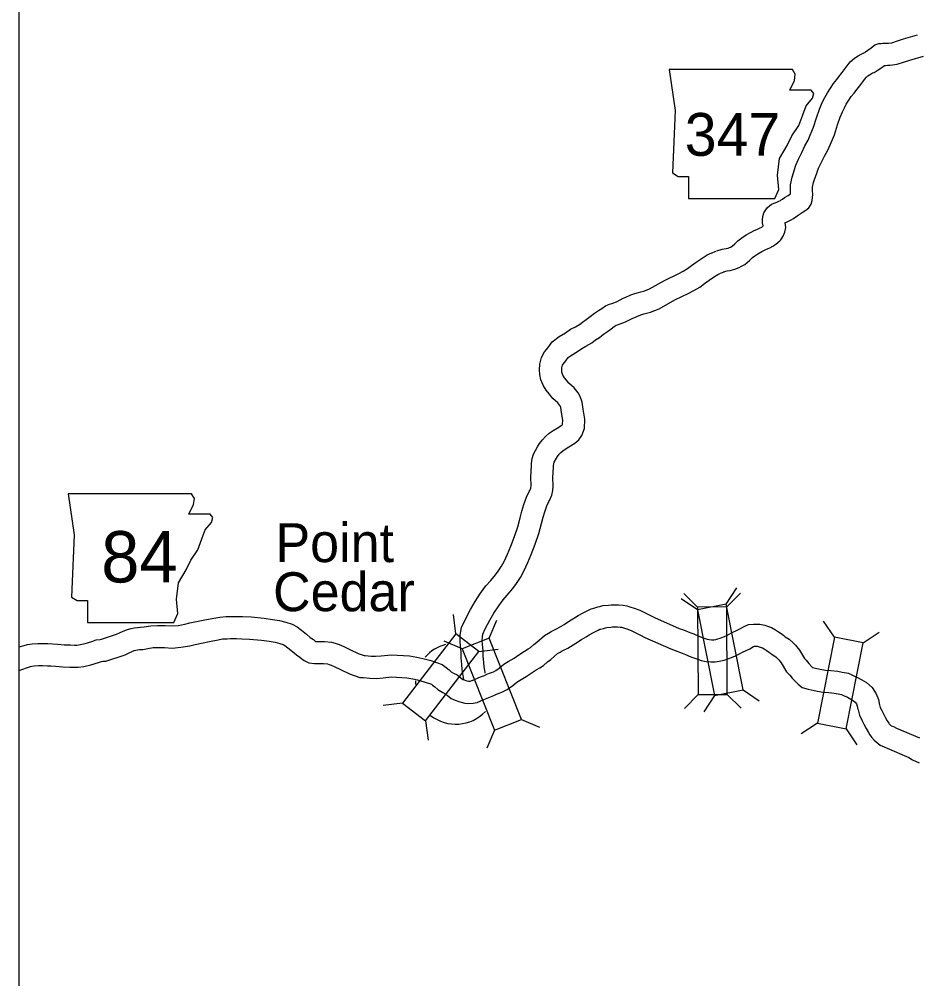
# Model space of a CAD drawing. Extents: x 1373862 to 1377080, y 1164775 to 1170415.
# Drawn here: x 1373884.5 to 1374006.5, y 1170176 to 1170306.2 of the extents above; entities that cross this region are included whole.
import ezdxf

# ---------------------------------------------------------------- set-up
doc = ezdxf.new("R2010")
doc.units = 0
doc.layers.add('1', color=7, linetype='Continuous')
doc.layers.add('Default', color=7, linetype='Continuous')

msp = doc.modelspace()

# ---------------------------------------------------------------- linework, layer by layer
at = {"layer": '1'}
msp.add_lwpolyline([(1373884.49, 1170388.77), (1374613.88, 1170388.77), (1374613.88, 1169861.94), (1373884.49, 1169861.94)], close=True, dxfattribs=at)
at = {"layer": 'Default'}
for p, q in [((1373976.57, 1170226.45), (1373974.69, 1170228.31)), ((1373980.44, 1170226.86), (1373981.91, 1170229.06)), ((1373980.53, 1170226.48), (1373982.38, 1170228.35)), ((1373976.55, 1170226.09), (1373974.36, 1170227.56)), ((1373943.77, 1170222.83), (1373943.43, 1170225.45)), ((1373948.29, 1170222.25), (1373949.33, 1170224.67)), ((1373995.14, 1170222.36), (1373993.67, 1170224.55)), ((1373999.03, 1170221.59), (1374001.22, 1170223.06)), ((1373944.61, 1170220.78), (1373942.19, 1170221.83)), ((1373946.9, 1170220.41), (1373949.52, 1170220.75)), ((1373982.75, 1170215.21), (1373984.94, 1170213.74)), ((1373976.64, 1170214.57), (1373974.79, 1170212.69)), ((1373978.86, 1170214.44), (1373977.4, 1170212.25)), ((1373980.6, 1170214.6), (1373982.48, 1170212.74)), ((1373936.51, 1170213.42), (1373933.9, 1170213.08)), ((1373952.69, 1170211.21), (1373955.11, 1170210.17)), ((1373939.65, 1170211), (1373939.99, 1170208.38)), ((1373992.84, 1170210.7), (1373990.65, 1170209.23)), ((1373996.73, 1170209.94), (1373998.2, 1170207.74)), ((1373949.01, 1170209.75), (1373947.97, 1170207.32))]:
    msp.add_line(p, q, dxfattribs=at)
for points in [[(1373979.18, 1170274.79), (1373979.91, 1170275.02), (1373980.43, 1170275.1), (1373980.73, 1170275.16), (1373980.92, 1170275.24), (1373981.05, 1170275.31), (1373981.25, 1170275.43), (1373981.62, 1170275.73), (1373982.05, 1170276.16), (1373982.57, 1170276.56), (1373983.18, 1170276.96), (1373983.84, 1170277.33), (1373984.23, 1170277.54), (1373984.62, 1170277.71), (1373985.06, 1170277.92), (1373985.28, 1170278.03), (1373985.38, 1170278.09), (1373985.49, 1170278.19), (1373985.38, 1170278.6), (1373985.37, 1170279.04), (1373985.42, 1170279.45), (1373985.58, 1170279.98), (1373985.83, 1170280.37), (1373986.07, 1170280.69), (1373986.59, 1170281.12), (1373987.11, 1170281.33), (1373987.44, 1170281.45), (1373987.6, 1170281.52), (1373987.83, 1170281.64), (1373987.93, 1170281.7), (1373988.08, 1170281.81), (1373988.38, 1170282.05), (1373988.85, 1170282.33), (1373989.07, 1170282.46), (1373989.19, 1170282.53), (1373989.19, 1170282.58), (1373989.18, 1170282.94), (1373989.18, 1170283.75), (1373989.41, 1170284.81), (1373989.57, 1170285.37), (1373989.93, 1170286.41), (1373990.26, 1170287.22), (1373990.7, 1170288.14), (1373991.13, 1170289.03), (1373991.57, 1170289.82), (1373991.87, 1170290.48), (1373992.32, 1170291.57), (1373992.71, 1170292.83), (1373993.13, 1170294.02), (1373993.5, 1170294.91), (1373993.84, 1170295.61), (1373994.19, 1170296.25), (1373994.61, 1170296.87), (1373995.01, 1170297.5), (1373995.47, 1170298.07), (1373995.71, 1170298.36), (1373996.2, 1170299.01), (1373996.61, 1170299.54), (1373996.87, 1170299.9), (1373997.3, 1170300.43), (1373997.89, 1170300.96), (1373998.35, 1170301.25), (1373998.76, 1170301.51), (1373999.13, 1170301.69), (1373999.26, 1170301.74), (1373999.37, 1170301.81), (1373999.68, 1170302.02), (1374000.12, 1170302.35), (1374000.61, 1170302.75), (1374001.19, 1170302.92), (1374001.47, 1170302.95), (1374001.73, 1170302.97), (1374001.99, 1170302.97), (1374002.26, 1170302.98), (1374002.49, 1170302.98), (1374002.96, 1170303.05), (1374003.69, 1170303.29), (1374004.51, 1170303.57), (1374006.42, 1170304.11)], [(1373980.09, 1170271.93), (1373980.58, 1170272.09), (1373980.98, 1170272.14), (1373981.65, 1170272.3), (1373982.2, 1170272.52), (1373982.53, 1170272.7), (1373982.97, 1170272.96), (1373983.62, 1170273.49), (1373984.04, 1170273.91), (1373984.32, 1170274.13), (1373984.73, 1170274.39), (1373985.28, 1170274.69), (1373985.56, 1170274.85), (1373985.85, 1170274.98), (1373986.38, 1170275.22), (1373986.78, 1170275.43), (1373987.2, 1170275.69), (1373987.72, 1170276.16), (1373987.86, 1170276.31), (1373988.18, 1170276.8), (1373988.42, 1170277.35), (1373988.55, 1170277.98), (1373988.48, 1170278.61), (1373988.47, 1170278.63), (1373988.55, 1170278.66), (1373988.92, 1170278.83), (1373989.28, 1170279.01), (1373989.59, 1170279.19), (1373989.9, 1170279.43), (1373990.09, 1170279.57), (1373990.38, 1170279.75), (1373990.62, 1170279.89), (1373990.92, 1170280.08), (1373991.28, 1170280.3), (1373991.68, 1170280.64), (1373991.97, 1170281.12), (1373992.11, 1170281.64), (1373992.15, 1170282.03), (1373992.2, 1170282.44), (1373992.18, 1170282.99), (1373992.18, 1170283.43), (1373992.32, 1170284.08), (1373992.43, 1170284.47), (1373992.74, 1170285.36), (1373993, 1170286.01), (1373993.4, 1170286.83), (1373993.8, 1170287.65), (1373994.25, 1170288.47), (1373994.62, 1170289.28), (1373995.15, 1170290.55), (1373995.56, 1170291.89), (1373995.93, 1170292.95), (1373996.23, 1170293.68), (1373996.5, 1170294.22), (1373996.76, 1170294.69), (1373997.11, 1170295.23), (1373997.44, 1170295.73), (1373997.81, 1170296.19), (1373998.07, 1170296.52), (1373998.59, 1170297.19), (1373999.01, 1170297.75), (1373999.25, 1170298.07), (1373999.49, 1170298.36), (1373999.7, 1170298.55), (1373999.93, 1170298.7), (1374000.25, 1170298.9), (1374000.32, 1170298.94), (1374000.53, 1170299.01), (1374000.97, 1170299.27), (1374001.44, 1170299.58), (1374001.94, 1170299.97), (1374002.07, 1170299.97), (1374002.34, 1170299.98), (1374002.73, 1170299.98), (1374003.66, 1170300.12), (1374004.64, 1170300.45), (1374005.39, 1170300.7), (1374007.24, 1170301.22)], [(1373944.84, 1170216.63), (1373944.77, 1170217.16), (1373944.63, 1170217.97), (1373944.59, 1170218.67), (1373944.48, 1170219.57), (1373944.46, 1170220.37), (1373944.4, 1170221.15), (1373944.35, 1170221.82), (1373944.36, 1170222.64), (1373944.54, 1170223.68), (1373945.05, 1170224.79), (1373945.73, 1170226.11), (1373946.38, 1170227.22), (1373947.12, 1170228.33), (1373947.84, 1170229.32), (1373948.49, 1170230.04), (1373949.16, 1170230.81), (1373949.52, 1170231.31), (1373949.96, 1170232.01), (1373950.31, 1170232.64), (1373950.75, 1170233.65), (1373951.2, 1170234.73), (1373951.71, 1170236.02), (1373952.16, 1170237.34), (1373952.49, 1170238.54), (1373952.7, 1170239.45), (1373952.99, 1170240.37), (1373953.36, 1170241.35), (1373953.71, 1170242.12), (1373953.79, 1170242.26), (1373953.94, 1170242.58), (1373953.95, 1170242.65), (1373953.96, 1170242.89), (1373953.93, 1170244.08), (1373954.01, 1170245.66), (1373954.04, 1170245.93), (1373954.14, 1170246.6), (1373954.3, 1170247.21), (1373954.82, 1170248.19), (1373955.13, 1170248.64), (1373955.5, 1170249.14), (1373955.91, 1170249.58), (1373956.42, 1170250.03), (1373956.99, 1170250.42), (1373957.52, 1170250.74), (1373958.16, 1170251.14), (1373958.2, 1170251.17), (1373958.23, 1170251.26), (1373958.26, 1170251.82), (1373958.1, 1170252.84), (1373957.99, 1170253.53), (1373957.91, 1170253.77), (1373957.88, 1170253.82), (1373957.62, 1170254.15), (1373956.93, 1170254.78), (1373956.42, 1170255.38), (1373956.04, 1170255.87), (1373955.67, 1170256.47), (1373955.28, 1170257.27), (1373955.16, 1170258), (1373955.12, 1170258.67), (1373955.18, 1170259.41), (1373955.4, 1170260.32), (1373955.78, 1170261.09), (1373956.28, 1170261.68), (1373956.81, 1170262.46), (1373957.78, 1170263.16), (1373958.63, 1170263.68), (1373959.34, 1170264.15), (1373959.98, 1170264.48), (1373960.56, 1170264.82), (1373960.97, 1170265.13), (1373961.46, 1170265.47), (1373962.01, 1170265.9), (1373962.6, 1170266.32), (1373963.12, 1170266.68), (1373963.57, 1170266.99), (1373964.07, 1170267.33), (1373964.5, 1170267.52), (1373965.05, 1170267.7), (1373965.55, 1170267.89), (1373966.08, 1170268.16), (1373966.49, 1170268.37), (1373966.74, 1170268.47), (1373967.53, 1170268.81), (1373968.06, 1170269.02), (1373968.53, 1170269.15), (1373968.86, 1170269.23), (1373969.26, 1170269.34), (1373970.05, 1170269.65), (1373972.09, 1170270.79), (1373974.03, 1170271.72), (1373974.6, 1170272.02), (1373975.21, 1170272.39), (1373975.75, 1170272.79), (1373976.38, 1170273.24), (1373977.04, 1170273.73), (1373977.88, 1170274.24), (1373978.51, 1170274.54), (1373979.11, 1170274.76)], [(1373947.76, 1170217.47), (1373947.74, 1170217.61), (1373947.62, 1170218.33), (1373947.57, 1170218.94), (1373947.47, 1170219.78), (1373947.46, 1170220.52), (1373947.39, 1170221.38), (1373947.35, 1170221.91), (1373947.36, 1170222.37), (1373947.43, 1170222.79), (1373947.75, 1170223.48), (1373948.35, 1170224.66), (1373948.92, 1170225.63), (1373949.58, 1170226.61), (1373950.18, 1170227.43), (1373950.74, 1170228.06), (1373951.51, 1170228.95), (1373952, 1170229.63), (1373952.53, 1170230.47), (1373953, 1170231.3), (1373953.51, 1170232.48), (1373953.98, 1170233.6), (1373954.52, 1170234.98), (1373955.03, 1170236.45), (1373955.4, 1170237.81), (1373955.6, 1170238.66), (1373955.82, 1170239.38), (1373956.13, 1170240.19), (1373956.39, 1170240.76), (1373956.47, 1170240.9), (1373956.8, 1170241.63), (1373956.94, 1170242.27), (1373956.97, 1170242.88), (1373956.93, 1170244.05), (1373957.01, 1170245.43), (1373957.02, 1170245.56), (1373957.08, 1170245.99), (1373957.12, 1170246.12), (1373957.4, 1170246.65), (1373957.56, 1170246.89), (1373957.8, 1170247.2), (1373958.01, 1170247.43), (1373958.27, 1170247.66), (1373958.61, 1170247.89), (1373959.09, 1170248.18), (1373959.92, 1170248.71), (1373960.47, 1170249.16), (1373960.88, 1170249.74), (1373961.2, 1170250.68), (1373961.28, 1170251.96), (1373961.06, 1170253.32), (1373960.91, 1170254.26), (1373960.65, 1170255.04), (1373960.35, 1170255.54), (1373959.81, 1170256.2), (1373959.1, 1170256.86), (1373958.76, 1170257.26), (1373958.52, 1170257.58), (1373958.3, 1170257.92), (1373958.17, 1170258.19), (1373958.14, 1170258.34), (1373958.13, 1170258.63), (1373958.15, 1170258.91), (1373958.24, 1170259.29), (1373958.32, 1170259.44), (1373958.67, 1170259.87), (1373958.99, 1170260.34), (1373959.45, 1170260.66), (1373960.25, 1170261.15), (1373960.86, 1170261.56), (1373961.42, 1170261.85), (1373962.23, 1170262.32), (1373962.72, 1170262.7), (1373963.24, 1170263.05), (1373963.81, 1170263.5), (1373964.33, 1170263.87), (1373964.82, 1170264.21), (1373965.27, 1170264.51), (1373965.52, 1170264.69), (1373965.57, 1170264.71), (1373966.05, 1170264.87), (1373966.78, 1170265.15), (1373967.43, 1170265.48), (1373967.76, 1170265.65), (1373967.92, 1170265.72), (1373968.66, 1170266.03), (1373969.01, 1170266.17), (1373969.29, 1170266.24), (1373969.62, 1170266.33), (1373970.2, 1170266.48), (1373971.34, 1170266.93), (1373973.47, 1170268.13), (1373975.39, 1170269.04), (1373976.07, 1170269.41), (1373976.89, 1170269.89), (1373977.52, 1170270.37), (1373978.14, 1170270.81), (1373978.71, 1170271.23), (1373979.31, 1170271.59), (1373979.69, 1170271.78), (1373980.17, 1170271.96)], [(1373945.97, 1170216.5), (1373947.12, 1170216.96), (1373947.66, 1170217.18), (1373947.96, 1170217.34), (1373948.45, 1170217.54), (1373948.85, 1170217.68), (1373949.2, 1170217.85), (1373949.66, 1170218.17), (1373950.28, 1170218.7), (1373950.88, 1170219.05), (1373951.67, 1170219.52), (1373952.31, 1170219.98), (1373953.08, 1170220.47), (1373953.56, 1170220.76), (1373953.87, 1170220.96), (1373954.36, 1170221.37), (1373954.77, 1170221.67), (1373955.8, 1170222.58), (1373956.33, 1170222.9), (1373956.71, 1170223.15), (1373957.52, 1170223.53), (1373958.46, 1170224.09), (1373959.18, 1170224.56), (1373959.87, 1170225), (1373960.38, 1170225.29), (1373961.04, 1170225.65), (1373961.38, 1170225.83), (1373961.77, 1170226.01), (1373962.12, 1170226.19), (1373962.48, 1170226.32), (1373963.03, 1170226.46), (1373963.3, 1170226.53), (1373963.72, 1170226.65), (1373964.47, 1170226.72), (1373964.83, 1170226.76), (1373965.34, 1170226.76), (1373965.83, 1170226.76), (1373966.47, 1170226.72), (1373966.99, 1170226.61), (1373967.39, 1170226.49), (1373967.96, 1170226.32), (1373968.75, 1170226.02), (1373970.17, 1170225.32), (1373970.71, 1170225.04), (1373974.09, 1170223.56), (1373974.64, 1170223.35), (1373975.54, 1170222.99), (1373976.05, 1170222.8), (1373976.76, 1170222.48), (1373977.32, 1170222.28), (1373977.87, 1170222.1), (1373978.13, 1170222.04), (1373978.45, 1170222.02), (1373978.76, 1170222.02), (1373979.03, 1170222.06), (1373979.33, 1170222.12), (1373979.65, 1170222.24), (1373980.08, 1170222.39), (1373980.45, 1170222.56), (1373980.85, 1170222.76), (1373981.18, 1170222.94), (1373981.95, 1170223.32), (1373982.3, 1170223.48), (1373982.79, 1170223.75), (1373983.49, 1170224.08), (1373984.15, 1170224.15), (1373984.64, 1170224.15), (1373985.04, 1170224.15), (1373985.68, 1170223.99), (1373986.2, 1170223.8), (1373986.62, 1170223.66), (1373987.14, 1170223.35), (1373987.54, 1170223.11), (1373987.9, 1170222.86), (1373988.27, 1170222.6), (1373988.48, 1170222.43), (1373989.01, 1170222.09), (1373989.55, 1170221.61), (1373989.86, 1170221.27), (1373990.39, 1170220.62), (1373991.07, 1170219.48), (1373991.32, 1170219.22), (1373991.69, 1170218.78), (1373992.06, 1170218.36), (1373992.17, 1170218.26), (1373992.34, 1170218.21), (1373992.97, 1170218.07), (1373993.93, 1170217.9), (1373994.66, 1170217.85), (1373995.59, 1170217.73), (1373996.2, 1170217.62), (1373997.04, 1170217.46), (1373997.67, 1170217.16), (1373998.27, 1170216.88), (1373998.85, 1170216.57), (1373999.49, 1170216.19), (1374000.26, 1170215.52), (1374000.8, 1170214.68), (1374001.13, 1170213.89), (1374001.28, 1170213.14)], [(1373895.67, 1170222.08), (1373897.71, 1170222.75), (1373898.09, 1170222.95), (1373898.6, 1170223.19), (1373899.18, 1170223.42), (1373899.69, 1170223.53), (1373900.07, 1170223.61), (1373900.54, 1170223.67), (1373900.94, 1170223.7), (1373901.47, 1170223.78), (1373902.35, 1170223.92), (1373903.24, 1170223.97), (1373904.3, 1170223.95), (1373905.21, 1170223.9), (1373906.07, 1170223.97), (1373906.99, 1170224.11), (1373907.64, 1170224.3), (1373909.7, 1170224.71), (1373910.91, 1170224.96), (1373911.71, 1170225.1), (1373912.59, 1170225.16), (1373913.12, 1170225.18), (1373914.03, 1170225.17), (1373914.78, 1170225.15), (1373915.97, 1170225.11), (1373917.75, 1170224.94), (1373918.89, 1170224.76), (1373919.83, 1170224.62), (1373920.66, 1170224.4), (1373921.52, 1170224.15), (1373922.21, 1170223.75), (1373922.79, 1170223.31), (1373923.49, 1170222.76), (1373923.99, 1170222.34), (1373924.42, 1170222.03), (1373924.71, 1170221.79), (1373924.79, 1170221.78), (1373925.15, 1170221.78), (1373925.91, 1170221.78), (1373926.86, 1170221.7), (1373927.39, 1170221.55), (1373927.94, 1170221.38), (1373928.55, 1170221.09), (1373929.37, 1170220.7), (1373930.49, 1170220.16), (1373931.32, 1170219.87), (1373931.46, 1170219.86), (1373932.25, 1170219.78), (1373932.86, 1170219.77), (1373933.6, 1170219.82), (1373934.96, 1170219.97), (1373937.46, 1170219.84), (1373938.47, 1170219.66), (1373939.28, 1170219.49), (1373940.36, 1170219.18), (1373941.92, 1170218.65), (1373942.46, 1170218.23), (1373942.86, 1170217.92), (1373943.11, 1170217.68), (1373943.46, 1170217.48), (1373943.94, 1170217.23), (1373944.42, 1170216.86), (1373944.7, 1170216.64), (1373944.87, 1170216.56), (1373945.1, 1170216.47), (1373945.25, 1170216.43), (1373945.47, 1170216.38), (1373945.52, 1170216.37), (1373945.7, 1170216.38), (1373945.95, 1170216.49)], [(1373947.11, 1170213.72), (1373948.25, 1170214.19), (1373948.91, 1170214.45), (1373949.2, 1170214.6), (1373949.52, 1170214.73), (1373950.02, 1170214.91), (1373950.72, 1170215.25), (1373951.49, 1170215.79), (1373952.02, 1170216.24), (1373952.42, 1170216.47), (1373953.32, 1170217.01), (1373953.99, 1170217.5), (1373954.65, 1170217.92), (1373955.15, 1170218.21), (1373955.65, 1170218.54), (1373956.21, 1170219.01), (1373956.65, 1170219.33), (1373957.57, 1170220.14), (1373957.92, 1170220.35), (1373958.19, 1170220.52), (1373958.94, 1170220.89), (1373960.04, 1170221.54), (1373960.8, 1170222.04), (1373961.43, 1170222.43), (1373961.85, 1170222.68), (1373962.43, 1170222.99), (1373962.72, 1170223.14), (1373963.09, 1170223.32), (1373963.31, 1170223.43), (1373963.39, 1170223.46), (1373963.78, 1170223.56), (1373964.06, 1170223.63), (1373964.26, 1170223.68), (1373964.79, 1170223.74), (1373965, 1170223.76), (1373965.33, 1170223.76), (1373965.72, 1170223.76), (1373966.06, 1170223.74), (1373966.26, 1170223.7), (1373966.53, 1170223.62), (1373966.99, 1170223.48), (1373967.55, 1170223.26), (1373968.82, 1170222.64), (1373969.43, 1170222.33), (1373972.95, 1170220.78), (1373973.54, 1170220.56), (1373974.46, 1170220.19), (1373974.91, 1170220.03), (1373975.64, 1170219.7), (1373976.34, 1170219.45), (1373977.08, 1170219.2), (1373977.73, 1170219.06), (1373978.38, 1170219.02), (1373978.95, 1170219.03), (1373979.51, 1170219.1), (1373980.16, 1170219.22), (1373980.69, 1170219.43), (1373981.18, 1170219.6), (1373981.73, 1170219.84), (1373982.26, 1170220.11), (1373982.58, 1170220.28), (1373983.24, 1170220.61), (1373983.65, 1170220.8), (1373984.15, 1170221.08), (1373984.3, 1170221.15), (1373984.3, 1170221.15), (1373984.65, 1170221.15), (1373984.67, 1170221.15), (1373984.8, 1170221.12), (1373985.21, 1170220.97), (1373985.37, 1170220.92), (1373985.59, 1170220.79), (1373985.89, 1170220.6), (1373986.19, 1170220.39), (1373986.47, 1170220.2), (1373986.71, 1170220), (1373987.18, 1170219.7), (1373987.44, 1170219.46), (1373987.6, 1170219.3), (1373987.93, 1170218.89), (1373988.66, 1170217.66), (1373989.09, 1170217.21), (1373989.42, 1170216.81), (1373989.89, 1170216.29), (1373990.22, 1170215.97), (1373990.79, 1170215.54), (1373991.59, 1170215.3), (1373992.38, 1170215.13), (1373993.58, 1170214.91), (1373994.37, 1170214.87), (1373995.13, 1170214.76), (1373995.66, 1170214.67), (1373996.1, 1170214.59), (1373996.39, 1170214.45), (1373996.92, 1170214.2), (1373997.37, 1170213.96), (1373997.73, 1170213.74), (1373997.97, 1170213.53), (1373998.13, 1170213.3), (1373998.24, 1170213.01), (1373998.34, 1170212.55)], [(1373884.49, 1170221.03), (1373885.17, 1170221.25), (1373885.61, 1170221.36), (1373886.26, 1170221.45), (1373887.01, 1170221.5), (1373887.68, 1170221.5), (1373888.39, 1170221.49), (1373888.99, 1170221.48), (1373889.72, 1170221.4), (1373890.58, 1170221.32), (1373891.45, 1170221.31), (1373891.99, 1170221.29), (1373892.29, 1170221.3), (1373892.78, 1170221.35), (1373893.44, 1170221.51), (1373894.35, 1170221.78), (1373894.94, 1170221.98), (1373895.48, 1170222.07), (1373895.67, 1170222.08)], [(1373896.26, 1170219.12), (1373898.86, 1170219.98), (1373899.4, 1170220.25), (1373899.8, 1170220.43), (1373900.08, 1170220.55), (1373900.3, 1170220.6), (1373900.56, 1170220.65), (1373900.83, 1170220.69), (1373901.25, 1170220.71), (1373901.95, 1170220.81), (1373902.67, 1170220.94), (1373903.29, 1170220.96), (1373904.2, 1170220.95), (1373905.25, 1170220.89), (1373906.42, 1170220.99), (1373907.64, 1170221.17), (1373908.36, 1170221.39), (1373910.3, 1170221.77), (1373911.48, 1170222.01), (1373912.08, 1170222.12), (1373912.73, 1170222.16), (1373913.16, 1170222.18), (1373913.99, 1170222.17), (1373914.69, 1170222.16), (1373915.77, 1170222.11), (1373917.37, 1170221.96), (1373918.42, 1170221.8), (1373919.23, 1170221.67), (1373919.86, 1170221.51), (1373920.32, 1170221.38), (1373920.55, 1170221.24), (1373920.97, 1170220.93), (1373921.59, 1170220.44), (1373922.14, 1170219.98), (1373922.59, 1170219.65), (1373922.85, 1170219.43), (1373923.19, 1170219.18), (1373923.81, 1170218.89), (1373924.57, 1170218.77), (1373925.17, 1170218.78), (1373925.79, 1170218.78), (1373926.32, 1170218.74), (1373926.55, 1170218.67), (1373926.84, 1170218.58), (1373927.25, 1170218.38), (1373928.09, 1170217.98), (1373929.34, 1170217.39), (1373930.72, 1170216.9), (1373931.22, 1170216.87), (1373932.06, 1170216.78), (1373932.94, 1170216.76), (1373933.88, 1170216.84), (1373935.04, 1170216.96), (1373937.12, 1170216.85), (1373937.9, 1170216.71), (1373938.55, 1170216.58), (1373939.47, 1170216.32), (1373940.47, 1170215.98), (1373940.61, 1170215.86), (1373940.92, 1170215.62), (1373941.3, 1170215.28), (1373942, 1170214.85), (1373942.33, 1170214.68), (1373942.59, 1170214.48), (1373943.13, 1170214.06), (1373943.68, 1170213.81), (1373944.15, 1170213.62), (1373944.5, 1170213.53), (1373945, 1170213.4), (1373945.46, 1170213.37), (1373946.09, 1170213.39), (1373946.63, 1170213.51), (1373947.13, 1170213.73)], [(1373884.49, 1170217.83), (1373885.46, 1170218.19), (1373886.02, 1170218.37), (1373886.19, 1170218.41), (1373886.54, 1170218.46), (1373887.12, 1170218.5), (1373887.67, 1170218.5), (1373888.33, 1170218.49), (1373888.8, 1170218.48), (1373889.42, 1170218.42), (1373890.42, 1170218.32), (1373891.38, 1170218.31), (1373891.96, 1170218.29), (1373892.49, 1170218.3), (1373893.28, 1170218.38), (1373894.23, 1170218.61), (1373895.26, 1170218.92), (1373895.66, 1170219.06), (1373895.84, 1170219.09), (1373896.26, 1170219.12)], [(1373998.35, 1170212.49), (1373998.53, 1170211.76), (1373998.91, 1170211.03), (1373999.16, 1170210.54), (1373999.44, 1170209.95), (1373999.77, 1170209.43), (1373999.96, 1170209.12), (1374000.17, 1170208.78), (1374000.53, 1170208.39), (1374000.79, 1170208.16), (1374001.34, 1170207.71), (1374001.91, 1170207.49), (1374002.31, 1170207.28), (1374005.25, 1170206.04), (1374005.76, 1170205.7), (1374006.63, 1170205.33)], [(1374001.27, 1170213.19), (1374001.35, 1170212.83), (1374001.57, 1170212.42), (1374001.85, 1170211.87), (1374002.07, 1170211.41), (1374002.32, 1170211.01), (1374002.52, 1170210.68), (1374002.57, 1170210.61), (1374002.63, 1170210.54), (1374002.73, 1170210.45), (1374002.87, 1170210.34), (1374003.15, 1170210.23), (1374003.59, 1170210), (1374006.69, 1170208.68)]]:
    msp.add_lwpolyline(points, dxfattribs=at)
for points in [[(1373972.71, 1170299.42), (1373973.55, 1170293.83), (1373973.18, 1170285.37), (1373973.92, 1170284.9), (1373975.32, 1170284.9), (1373975.32, 1170281.92), (1373987.04, 1170281.92), (1373987.6, 1170283.13), (1373987.41, 1170285.09), (1373987.69, 1170287.32), (1373988.71, 1170289.09), (1373989.37, 1170290.39), (1373990.3, 1170291.79), (1373990.85, 1170293.27), (1373991.32, 1170294.48), (1373992.16, 1170295.51), (1373992.34, 1170296.16), (1373991.97, 1170296.62), (1373989.09, 1170296.62), (1373989.74, 1170297.93), (1373989.83, 1170298.76), (1373989.45, 1170299.41)], [(1373891.14, 1170241.84), (1373891.97, 1170236.26), (1373891.6, 1170227.79), (1373892.34, 1170227.33), (1373893.74, 1170227.33), (1373893.74, 1170224.35), (1373905.46, 1170224.35), (1373906.02, 1170225.56), (1373905.84, 1170227.51), (1373906.12, 1170229.75), (1373907.14, 1170231.52), (1373907.79, 1170232.82), (1373908.72, 1170234.21), (1373909.28, 1170235.7), (1373909.75, 1170236.91), (1373910.58, 1170237.94), (1373910.77, 1170238.59), (1373910.4, 1170239.05), (1373907.51, 1170239.05), (1373908.16, 1170240.35), (1373908.26, 1170241.19), (1373907.87, 1170241.84)], [(1373976.55, 1170226.09), (1373978.86, 1170214.44), (1373982.75, 1170215.21), (1373980.44, 1170226.86)], [(1373980.6, 1170214.6), (1373980.53, 1170226.48), (1373976.57, 1170226.45), (1373976.64, 1170214.57)], [(1373939.65, 1170211), (1373946.9, 1170220.41), (1373943.77, 1170222.83), (1373936.51, 1170213.42)], [(1373944.61, 1170220.78), (1373949.01, 1170209.75), (1373952.69, 1170211.21), (1373948.29, 1170222.25)], [(1373996.73, 1170209.94), (1373999.03, 1170221.59), (1373995.14, 1170222.36), (1373992.84, 1170210.7)]]:
    msp.add_lwpolyline(points, close=True, dxfattribs=at)
for start, end in [(104.6734, 138.959), (176.1329, 180.9903), (231.4918, 316.9545)]:
    msp.add_arc((1373943.76, 1170216.05), 5.5, start, end, dxfattribs=at)

# ---------------------------------------------------------------- texts
for s, height, p in [('347', 5.808, (1373974.83, 1170287.7)), ('Point', 5.28, (1373919.27, 1170232.55)), ('84', 6.97, (1373895.62, 1170229.79)), ('Cedar', 5.28, (1373918.95, 1170225.89))]:
    msp.add_text(s, height=height, dxfattribs=at).set_placement(p)

doc.saveas('drawing.dxf')
